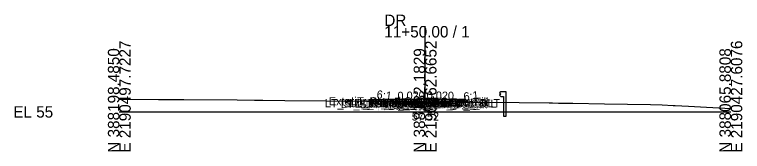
# Model space of a CAD drawing. Extents: x -26 to 153, y 490 to 1524.
# Drawn here: x -25.7 to 152.8, y 1490.3 to 1523.9 of the extents above; entities that cross this region are included whole.
import ezdxf

# ---------------------------------------------------------------- set-up
doc = ezdxf.new("R2010")
doc.units = 0
for name, color, linetype in [('Default', 7, 'Continuous'), ('Exist CMT Ground Line', 7, 'Continuous'), ('Exist Cross Section Cell', 7, 'Continuous'), ('Exist XS Center Line Elevation Label', 7, 'Continuous'), ('Prop CMT Guardrail Graphics', 7, 'Continuous'), ('Prop CMT Pvmt Course 1', 7, 'Continuous'), ('Prop CMT Pvmt Course 2', 7, 'Continuous'), ('Prop CMT Pvmt Surface', 7, 'Continuous'), ('Prop CMT Shld Paved Course 1', 7, 'Continuous'), ('Prop CMT Shld Paved Course 2', 7, 'Continuous'), ('Prop CMT Slope Grass', 7, 'Continuous'), ('Prop CMT Subgrade Earthwork', 7, 'Continuous'), ('Prop XS SE Text', 7, 'Continuous'), ('Prop XS Side Slope Text', 7, 'Continuous'), ('Scratch_Level_1', 7, 'Continuous')]:
    doc.layers.add(name, color=color, linetype=linetype)

msp = doc.modelspace()

# ---------------------------------------------------------------- linework, layer by layer
at = {"layer": 'Exist CMT Ground Line'}
for p, q in [((0, 1503.14), (9.62, 1503.07)), ((9.62, 1503.07), (15.85, 1503.02)), ((15.85, 1503.02), (28.87, 1502.92)), ((28.87, 1502.92), (33.15, 1502.89)), ((33.15, 1502.89), (35.18, 1502.87)), ((35.18, 1502.87), (40.58, 1502.83)), ((40.58, 1502.83), (60.62, 1502.65)), ((60.62, 1502.65), (66.94, 1502.6)), ((66.94, 1502.6), (75, 1502.52)), ((75, 1502.52), (79.88, 1502.48)), ((79.88, 1502.48), (80.48, 1502.48)), ((80.48, 1502.48), (85.96, 1502.43)), ((85.96, 1502.43), (86.59, 1502.42)), ((86.59, 1502.42), (87.53, 1502.41)), ((87.53, 1502.41), (98.07, 1502.32)), ((98.07, 1502.32), (105.46, 1502.19)), ((105.46, 1502.19), (106.29, 1502.18)), ((106.29, 1502.18), (107.73, 1502.16)), ((107.73, 1502.16), (110.18, 1502.11)), ((110.18, 1502.11), (111.2, 1502.1)), ((111.2, 1502.1), (118.97, 1501.97)), ((118.97, 1501.97), (130.3, 1501.78)), ((130.3, 1501.78), (133.16, 1501.74)), ((133.16, 1501.74), (135.88, 1501.58)), ((135.88, 1501.58), (136.34, 1501.56)), ((136.34, 1501.56), (139.58, 1501.38)), ((139.58, 1501.38), (150, 1500.79))]:
    msp.add_line(p, q, dxfattribs=at)
at = {"layer": 'Exist Cross Section Cell'}
for p, q in [((75, 1500), (75, 1521.05)), ((0, 1500), (75, 1500)), ((75, 1500), (150, 1500))]:
    msp.add_line(p, q, dxfattribs=at)
at = {"layer": 'Prop CMT Guardrail Graphics'}
for points in [[(94.89, 1504.93), (93.55, 1504.93), (93.28, 1504.64)], [(93.28, 1504.64), (93.55, 1504.35)], [(93.55, 1504.35), (93.28, 1504.06)], [(93.28, 1504.06), (93.55, 1503.76), (94.22, 1503.76)], [(94.22, 1503.76), (94.22, 1498.93)], [(94.89, 1498.93), (94.89, 1504.93)], [(94.22, 1498.93), (94.89, 1498.93)]]:
    msp.add_lwpolyline(points, dxfattribs=at)
at = {"layer": 'Prop CMT Pvmt Course 1'}
for points in [[(75, 1502.29), (69.5, 1502.18)], [(69.5, 1502.17), (75, 1502.28)], [(69.5, 1502.18), (69.5, 1502.17)], [(75, 1502.28), (75, 1502.29)], [(75, 1502.29), (80.5, 1502.18)], [(75, 1502.28), (75, 1502.29)], [(80.5, 1502.17), (75, 1502.28)], [(80.5, 1502.18), (80.5, 1502.17)]]:
    msp.add_lwpolyline(points, dxfattribs=at)
msp.add_lwpolyline([(75, 1502.28), (75, 1502.16), (75, 1502.16), (75, 1502.28)], close=True, dxfattribs=at)
msp.add_lwpolyline([(75, 1502.28), (75, 1502.16), (75, 1502.16), (75, 1502.28)], close=True, dxfattribs=at)
at = {"layer": 'Prop CMT Pvmt Course 2'}
for points in [[(75, 1502.28), (69.5, 1502.17)], [(69.5, 1502.17), (69.5, 1501.92)], [(69.5, 1501.92), (75, 1502.03)], [(75, 1502.03), (75, 1502.28)], [(75, 1502.03), (75, 1502.28)], [(75, 1502.28), (80.5, 1502.17)], [(80.5, 1501.92), (75, 1502.03)], [(80.5, 1502.17), (80.5, 1501.92)]]:
    msp.add_lwpolyline(points, dxfattribs=at)
at = {"layer": 'Prop CMT Pvmt Surface'}
for points in [[(75, 1502.29), (69.5, 1502.18)], [(75, 1502.29), (80.5, 1502.18)]]:
    msp.add_lwpolyline(points, dxfattribs=at)
at = {"layer": 'Prop CMT Shld Paved Course 1'}
for points in [[(69.5, 1502.18), (69.49, 1502.17)], [(69.49, 1502.17), (69.5, 1502.17)], [(69.5, 1502.17), (69.5, 1502.18)], [(80.5, 1502.18), (80.51, 1502.17)], [(80.5, 1502.17), (80.5, 1502.18)], [(80.51, 1502.17), (80.5, 1502.17)]]:
    msp.add_lwpolyline(points, dxfattribs=at)
at = {"layer": 'Prop CMT Shld Paved Course 2'}
for points in [[(69.5, 1502.17), (69.49, 1502.17), (69.49, 1502.17), (69.23, 1501.91)], [(69.23, 1501.91), (69.5, 1501.92)], [(69.5, 1501.92), (69.5, 1502.17)], [(80.5, 1502.17), (80.51, 1502.17), (80.51, 1502.17), (80.77, 1501.91)], [(80.5, 1501.92), (80.5, 1502.17)], [(80.77, 1501.91), (80.5, 1501.92)]]:
    msp.add_lwpolyline(points, dxfattribs=at)
at = {"layer": 'Prop CMT Slope Grass'}
for p, q in [((63.86, 1502.62), (67.5, 1502.02)), ((85.01, 1502.44), (82.5, 1502.02))]:
    msp.add_line(p, q, dxfattribs=at)
for points in [[(69.5, 1502.18), (67.5, 1502.02)], [(80.5, 1502.18), (82.5, 1502.02)], [(80.5, 1502.18), (82.5, 1502.02)]]:
    msp.add_lwpolyline(points, dxfattribs=at)
at = {"layer": 'Prop CMT Subgrade Earthwork'}
for points in [[(69.5, 1501.92), (69.23, 1501.91), (69.01, 1502.14)], [(75, 1502.03), (69.5, 1501.92)], [(75, 1502.03), (80.5, 1501.92)], [(80.5, 1501.92), (80.77, 1501.91), (80.99, 1502.14)]]:
    msp.add_lwpolyline(points, dxfattribs=at)

# ---------------------------------------------------------------- texts
at = {"layer": 'Default'}
msp.add_text('-', height=0.0001, dxfattribs=at).set_placement((0, 1500))
at = {"layer": 'Exist Cross Section Cell'}
for s, p in [('DR', (65, 1521.05)), ('11+50.00 / 1', (65, 1518.25)), ('EL 55', (-26, 1498.6))]:
    msp.add_text(s, height=2.8, dxfattribs=at).set_placement(p)
for s, p in [('E 2190497.7227', (2.8, 1490)), ('E 2190462.6652', (77.8, 1490)), ('E 2190427.6076', (152.8, 1490)), ('N 388198.4850', (0, 1490)), ('N 388132.1829', (75, 1490)), ('N 388065.8808', (150, 1490))]:
    msp.add_text(s, height=2.8, rotation=90, dxfattribs=at).set_placement(p)
at = {"layer": 'Exist XS Center Line Elevation Label'}
msp.add_text('57.52', height=2, dxfattribs=at).set_placement((71.73, 1497.87))
at = {"layer": 'Prop XS SE Text'}
for rotation, p in [(1.1458, (68.25, 1502.92)), (358.8542, (75.37, 1503.06))]:
    msp.add_text('0.020', height=2, rotation=rotation, dxfattribs=at).set_placement(p)
at = {"layer": 'Prop XS Side Slope Text'}
for rotation, p in [(352.4117, (63.01, 1503.36)), (5.9169, (84.53, 1502.74))]:
    msp.add_text('6:1', height=2, rotation=rotation, dxfattribs=at).set_placement(p)
at = {"layer": 'Scratch_Level_1'}
for s, p in [('LT_Sub_Trench_Out_DLT', (50.42, 1501.15)), ('Exterior Boundary', (51.37, 1501.59)), ('LT_PS2_Shelf_Out', (56.32, 1501.18)), ('LT_Slope_Cut', (56.87, 1501.59)), ('RT_Sub_Trench_Out_DLT', (61.43, 1501.14)), ('RT_PV2_OEEOP', (64.26, 1501.28)), ('LT_PV2_OEEOP', (64.31, 1501.28)), ('RT_PV2_IEEOP', (64.91, 1501.28)), ('LT_PV2_IEEOP', (64.95, 1501.28)), ('RT_PS2_Shelf_Out', (66.37, 1501.17)), ('Exterior Boundary', (67.43, 1501.45)), ('PV2_PGL', (68.91, 1501.28)), ('PV1_PGL', (69.47, 1501.29)), ('RT_Slope_Cut', (72.87, 1501.45)), ('RT_Slope_Fill', (73.76, 1501.45)), ('LT_Sub_Trench_Out', (54.29, 1500.93)), ('LT_GS_OS_CTL', (57.72, 1501.03)), ('LT_Sub_OEOT', (60.43, 1500.93)), ('LT_PV2_OEOT', (60.52, 1501.18)), ('LT_PS2_OEOP', (60.58, 1501.18)), ('LT_PV1_OEOT', (61.09, 1501.19)), ('RT_Sub_OEEOP', (64.17, 1501.03)), ('LT_Sub_OEEOP', (64.21, 1501.03)), ('RT_PV1_OEEOP', (64.83, 1501.16)), ('RT_Sub_Trench_Out', (64.84, 1500.91)), ('LT_PV1_OEEOP', (64.87, 1501.16)), ('RT_PV1_IEEOP', (65.47, 1501.16)), ('LT_PV1_IEEOP', (65.52, 1501.16)), ('RT_Sub_OEOT', (70.45, 1500.92)), ('RT_PV2_OEOT', (70.55, 1501.17)), ('RT_PS2_OEOP', (70.62, 1501.17)), ('RT_PV1_OEOT', (71.11, 1501.18)), ('RT_GS_OS_CTL', (71.74, 1501.02))]:
    msp.add_text(s, height=2, dxfattribs=at).set_placement(p)

doc.saveas('drawing.dxf')
